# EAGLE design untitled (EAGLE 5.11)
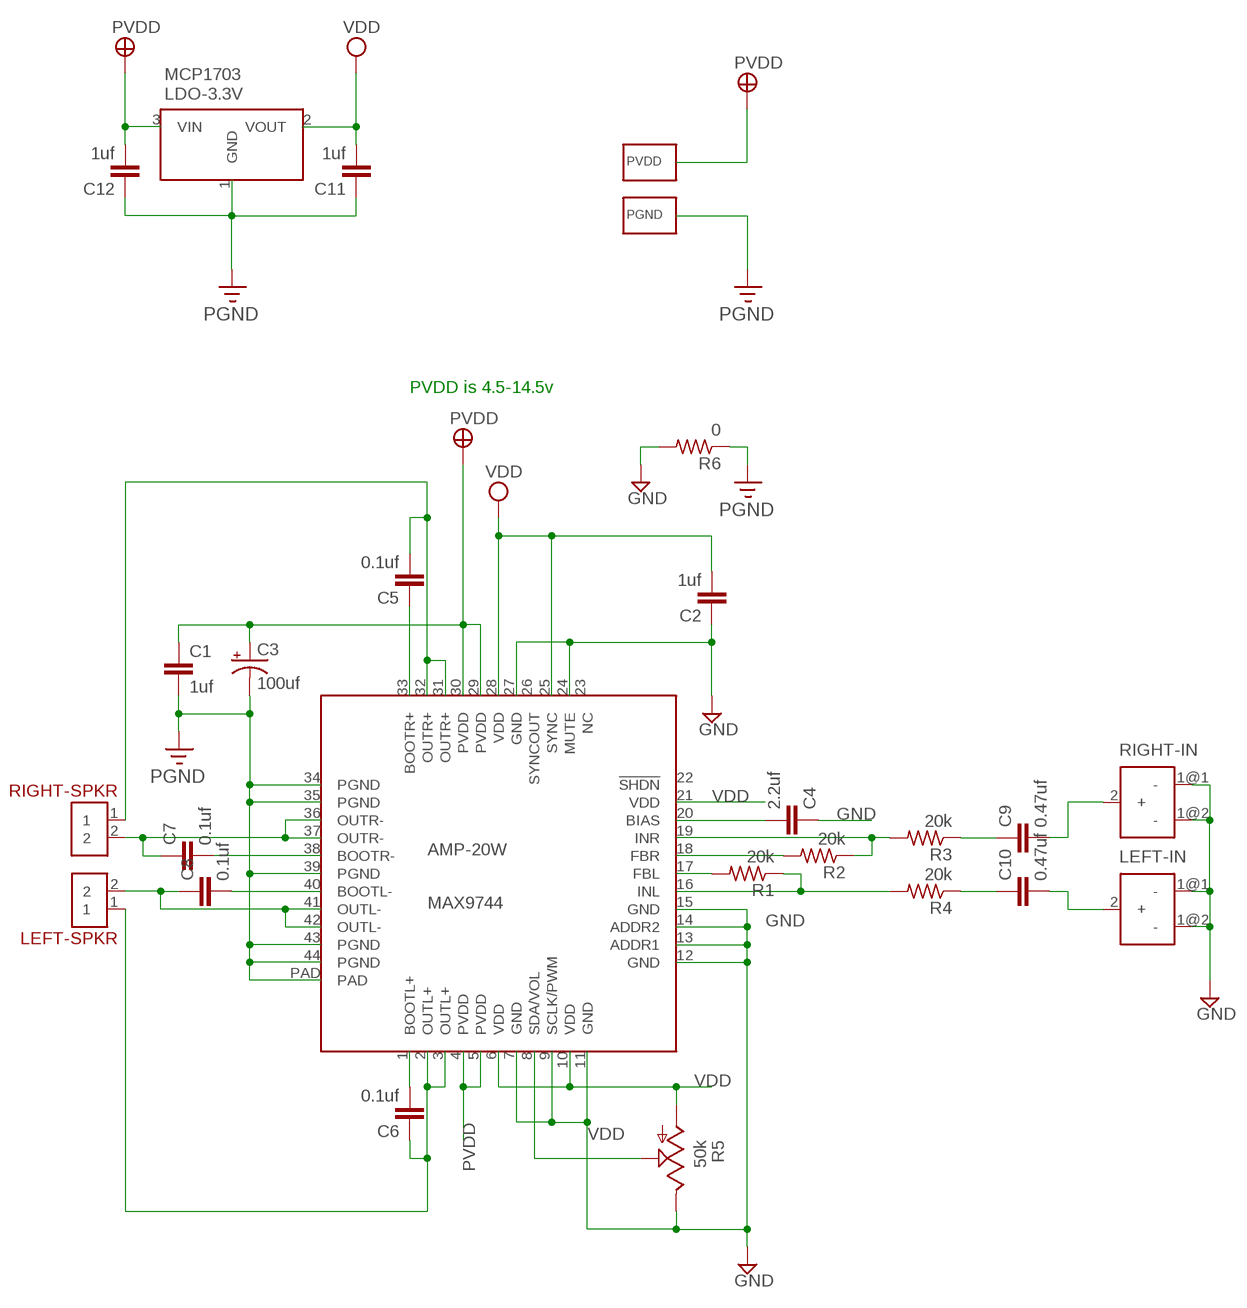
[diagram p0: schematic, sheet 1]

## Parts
AMP-20W  MAX9744  [QFN44-7X7-POWERPAD]
C1  1uf  C-EUC0805  [C0805]
C2  1uf  C-EUC0805  [C0805]
C3  100uf  CPOL-USE  [PANASONIC_E]
C4  2.2uf  C-EUC1206  [C1206]
C5  0.1uf  C-EUC0805  [C0805]
C6  0.1uf  C-EUC0805  [C0805]
C7  0.1uf  C-EUC0805  [C0805]
C8  0.1uf  C-EUC0805  [C0805]
C9  0.47uf  C-EUC1206  [C1206]
C10  0.47uf  C-EUC1206  [C1206]
C11  1uf  C-EUC0805  [C0805]
C12  1uf  C-EUC0805  [C0805]
LDO-3.3V  MCP1703  [SOT23-3]
LEFT-IN  AUDIO-JACK-MONO  [AUDIO-JACK-MONO-SMD]
LEFT-SPKR  SCREW-CLAMP-2X3.5MM  [SCREW-CLAMP-2X3.5MM]
PGND  WIREPAD-SMD-NO-VALUE5X5MM  [WIREPAD-SMD-5X5MM]
PVDD  WIREPAD-SMD-NO-VALUE5X5MM  [WIREPAD-SMD-5X5MM]
R1  20k  R-US_R0805  [R0805]
R2  20k  R-US_R0805  [R0805]
R3  20k  R-US_R0805  [R0805]
R4  20k  R-US_R0805  [R0805]
R5  50k  POT-TRIM-PARALLAX  [POT-TRIM-PARALLAX]
R6  0  R-US_R1206  [R1206]
RIGHT-IN  AUDIO-JACK-MONO  [AUDIO-JACK-MONO-SMD]
RIGHT-SPKR  SCREW-CLAMP-2X3.5MM  [SCREW-CLAMP-2X3.5MM]

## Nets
GND: AMP-20W.7(GND) AMP-20W.9(SCLK/PWM) AMP-20W.11(GND) AMP-20W.12(GND) AMP-20W.13(ADDR1) AMP-20W.14(ADDR2) AMP-20W.15(GND) AMP-20W.24(MUTE) AMP-20W.27(GND) C2.1 C4.1 LEFT-IN.1@1(-) LEFT-IN.1@2(-) R5.3(E) R6.2 RIGHT-IN.1@1(-) RIGHT-IN.1@2(-)
N$1: AMP-20W.16(INL) R1.1 R4.2
N$2: AMP-20W.18(FBR) R2.2
N$3: AMP-20W.17(FBL) R1.2
N$4: AMP-20W.19(INR) R2.1 R3.2
N$5: AMP-20W.36(OUTR-) AMP-20W.37(OUTR-) C7.1 RIGHT-SPKR.2
N$6: C10.1 R4.1
N$7: AMP-20W.41(OUTL-) AMP-20W.42(OUTL-) C8.1 LEFT-SPKR.2
N$8: AMP-20W.40(BOOTL-) C8.2
N$9: AMP-20W.38(BOOTR-) C7.2
N$10: AMP-20W.2(OUTL+) AMP-20W.3(OUTL+) C6.1 LEFT-SPKR.1
N$11: AMP-20W.31(OUTR+) AMP-20W.32(OUTR+) C5.2 RIGHT-SPKR.1
N$12: AMP-20W.20(BIAS) C4.2
N$13: AMP-20W.1(BOOTL+) C6.2
N$14: AMP-20W.33(BOOTR+) C5.1
N$15: C9.1 R3.1
N$17: AMP-20W.8(SDA/VOL) R5.2(S)
N$19: C9.2 RIGHT-IN.2(+)
N$20: C10.2 LEFT-IN.2(+)
PGND: AMP-20W.34(PGND) AMP-20W.35(PGND) AMP-20W.39(PGND) AMP-20W.43(PGND) AMP-20W.44(PGND) AMP-20W.PAD C1.2 C3.- C11.1 C12.1 LDO-3.3V.1(GND) PGND.1(P) R6.1
PVDD: AMP-20W.4(PVDD) AMP-20W.5(PVDD) AMP-20W.29(PVDD) AMP-20W.30(PVDD) C1.1 C3.+ C12.2 LDO-3.3V.3(VIN) PVDD.1(P)
VDD: AMP-20W.6(VDD) AMP-20W.10(VDD) AMP-20W.21(VDD) AMP-20W.25(SYNC) AMP-20W.28(VDD) C2.2 C11.2 LDO-3.3V.2(VOUT) R5.1(A)
Unconnected: AMP-20W.22(!SHDN) AMP-20W.23(NC) AMP-20W.26(SYNCOUT)

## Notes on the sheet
- PVDD is 4.5-14.5v

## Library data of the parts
AMP-20W = trl:MAX9744
C1 C2 C4-C12 = rcl:C-EU: CAPACITOR, European symbol
C3 = rcl:CPOL-US: POLARIZED CAPACITOR, American symbol
LDO-3.3V = trl:MCP1703
LEFT-IN RIGHT-IN = trl:AUDIO-JACK-MONO
LEFT-SPKR RIGHT-SPKR = trl:SCREW-CLAMP-2X3.5MM
PGND PVDD = trl:WIREPAD-SMD-NO-VALUE
R1-R4 R6 = resistor:R-US_: RESISTOR, American symbol
R5 = trl:POT-TRIM-PARALLAX: POTENTIOMETER

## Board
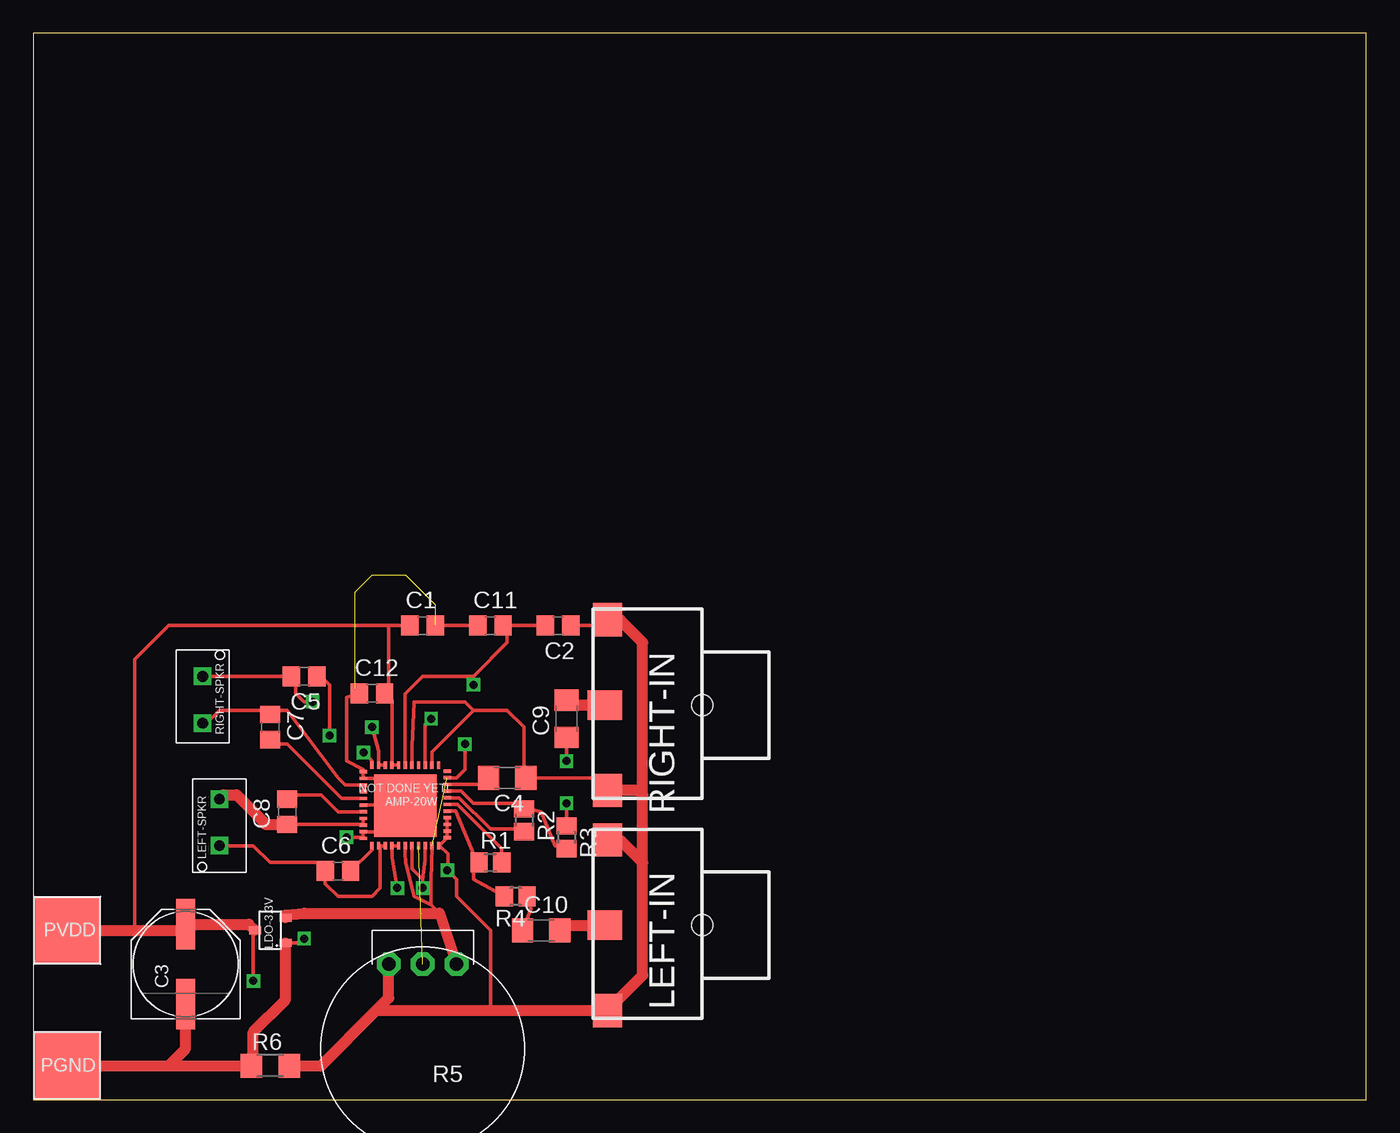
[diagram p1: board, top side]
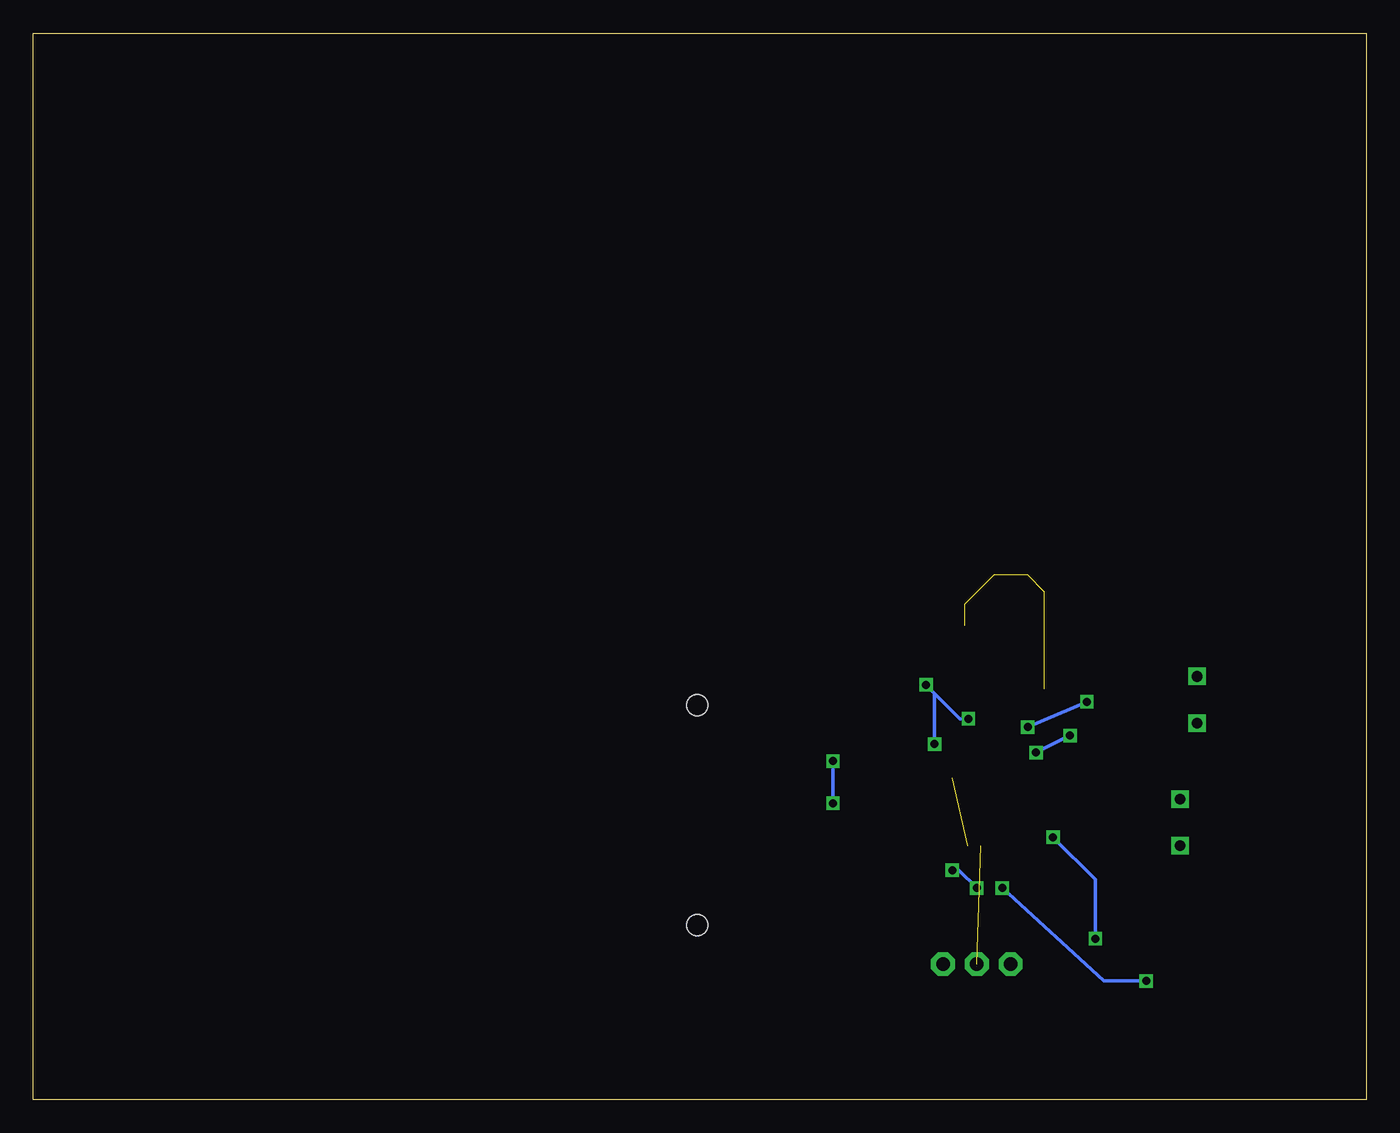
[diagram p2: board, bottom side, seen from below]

Size 100 x 80 mm. Coordinates in mm from the lower left corner, seen from the top.
Outline: 0,0 100,0 100,80 0,80 0,0
Copper layers (1*16): Top 0.035mm / dielectric 1.5mm / Bottom 0.035mm
Design rules "default": minimum track width 10mil, minimum drill 0.6mm, track to track 8mil, track to pad 8mil, pad to pad 8mil, via to via 8mil, smd to smd 8mil, copper to edge 40mil, drill to drill 8mil, minimum pad ring 10mil, minimum via ring 8mil, stop-mask expansion 4mil, vias tented up to drill 0mil, thermal gap 10mil

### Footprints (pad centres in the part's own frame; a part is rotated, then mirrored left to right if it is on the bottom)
QFN44-7X7-POWERPAD = smd 0.25 x 0.55: 1 0,0; 2 0.5,0; 3 1,0; 4 1.5,0; 5 2,0; 6 2.5,0; 7 3,0; 8 3.5,0; 9 4,0; 10 4.5,0; 11 5,0; 23 5,6.05; 24 4.5,6.05; 25 4,6.05; 26 3.5,6.05; 27 3,6.05; 28 2.5,6.05; 29 2,6.05; 30 1.5,6.05; 31 1,6.05; 32 0.5,6.05; 33 0,6.05 | smd 0.55 x 0.25: 12 5.65,0.6; 13 5.65,1.1; 14 5.65,1.6; 15 5.65,2.1; 16 5.65,2.6; 17 5.65,3.1; 18 5.65,3.6; 19 5.65,4.1; 20 5.65,4.6; 21 5.65,5.1; 22 5.65,5.6; 34 -0.65,5.55; 35 -0.65,5.05; 36 -0.65,4.55; 37 -0.65,4.05; 38 -0.65,3.55; 39 -0.65,3.05; 40 -0.65,2.55; 41 -0.65,2.05; 42 -0.65,1.55; 43 -0.65,1.05; 44 -0.65,0.55 | smd 4.7 x 4.7: PAD 2.5,3
C0805 = smd 1.3 x 1.5: 1 -0.95,0; 2 0.95,0
PANASONIC_E = smd 3.8 x 1.4: + 3,0; - -3,0
C1206 = smd 1.6 x 1.8: 1 -1.4,0; 2 1.4,0
SOT23-3 = smd 0.6 x 0.9: 1 -0.95,-1.15; 2 0.95,-1.15; 3 0,1.15
AUDIO-JACK-MONO-SMD = smd 2.2 x 2.5: 1@1 0.1,-14.4; 1@2 0.1,-1.6 | smd 2.6 x 2.2: 2 0.3,-8 | hole 1.6: -7,-8
SCREW-CLAMP-2X3.5MM = drill 0.8 square: 1 0,0; 2 3.5,0
WIREPAD-SMD-5X5MM = smd 5 x 5: 1 0,0
R0805 = smd 1.3 x 1.5: 1 -0.85,0; 2 0.85,0
POT-TRIM-PARALLAX = drill 1.016 pad 1.778 octagon: 1 -2.54,-3.81; 2 0,-3.81; 3 2.54,-3.81
R1206 = smd 1.6 x 1.803: 1 -1.422,0; 2 1.422,0

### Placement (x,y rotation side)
AMP-20W  25.4,19.05 0 top
C1  29.21,35.56 0 top
C2  39.37,35.56 180 top
C3  11.43,10.16 90 top
C4  35.56,24.13 180 top
C5  20.32,31.75 180 top
C6  22.86,17.14 0 top
C7  17.78,27.94 270 top
C8  19.05,21.59 90 top
C9  40.01,28.57 90 top
C10  38.1,12.7 0 top
C11  34.29,35.56 0 top
C12  25.4,30.48 0 top
LDO-3.3V  17.78,12.7 90 top
LEFT-IN  43.18,5.08 180 top
LEFT-SPKR  13.97,19.05 90 top
PGND  2.54,2.54 90 top
PVDD  2.54,12.7 90 top
R1  34.29,17.78 0 top
R2  36.83,20.95 270 top
R3  40.01,19.68 270 top
R4  36.2,15.24 180 top
R5  29.21,6.35 180 top
R6  17.78,2.54 0 top
RIGHT-IN  43.18,21.59 180 top
RIGHT-SPKR  12.7,31.75 270 top

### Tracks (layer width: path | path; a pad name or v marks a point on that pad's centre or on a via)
GND  (via drill 0.6)
  Top 0.254: AMP-20W.12 AMP-20W.13 AMP-20W.14 AMP-20W.15 | AMP-20W.12 31,19.65 | RIGHT-IN.1@2 42.14,24.13 C4.1 36.83,24.26 36.83,27.94 35.56,29.21 33.02,29.21 | 34.29,6.68 34.29,12.7 31.75,15.24 31.75,16.51 v31.05,17.21 31.11,17.27 31.11,18.41 30.48,19.05 AMP-20W.11 30.45,19.05 AMP-20W.12 | AMP-20W.9 29.4,17.97 29.21,16.51 | AMP-20W.7 28.4,17.32 29.21,16.51 | C2.1 42.65,35.56 RIGHT-IN.1@1 | v29.21,15.88 29.21,16.51 | AMP-20W.27 28.4,26.5 28.57,29.84 32.38,29.84 33.02,29.21 | AMP-20W.24 29.9,26.09 33.02,29.21
  Top 0.813: 25.73,6.68 26.67,7.62 R5.3 | 25.73,6.68 34.29,6.68 LEFT-IN.1@2 45.72,9.32 45.72,17.78 | LEFT-IN.1@1 44.02,19.48 45.72,17.78 | RIGHT-IN.1@2 45.39,23.19 45.72,22.86 | 45.72,17.78 45.72,22.86 | RIGHT-IN.1@1 44.02,35.99 45.72,34.29 45.72,22.86 | R6.2 21.59,2.54 25.73,6.68
  Bottom 0.254: v31.05,17.21 30.55,17.21 v29.21,15.88
N$1
  Top 0.254: R4.2 33.02,16.51 33.02,17.36 R1.1 33.02,18.2 33.02,18.41 31.69,21.65 AMP-20W.16
N$2
  Top 0.254: AMP-20W.18 31.96,22.65 34.29,20.32 36.62,20.32 R2.2
N$3
  Top 0.254: AMP-20W.17 31.82,22.15 35.14,18.84 R1.2
N$4
  Top 0.254: AMP-20W.19 32.09,23.15 33.02,22.23 36.41,22.23 R2.1 37.25,21.8 38.1,21.59 39.16,19.05 R3.2
N$5
  Top 0.254: AMP-20W.37 AMP-20W.36 23.39,23.6 22.86,24.13 19.05,29.21 18.1,29.21 C7.1 17.46,29.21 13.97,29.21 13.01,28.25 RIGHT-SPKR.2
N$6
  Top 0.254: C10.1 37.34,14.31 R4.1
N$7
  Top 0.254: AMP-20W.41 AMP-20W.42 24.71,20.64 C8.1
  Top 0.813: C8.1 17.46,20.64 15.24,22.86 14.28,22.86 LEFT-SPKR.2
N$8
  Top 0.254: AMP-20W.40 22.85,21.6 21.59,22.86 19.37,22.86 C8.2
N$9
  Top 0.254: AMP-20W.38 23.12,22.6 19.05,26.67 18.1,26.67 C7.2
N$10
  Top 0.254: AMP-20W.3 AMP-20W.2 26.04,18.91 26.04,15.88 25.4,15.24 22.86,15.24 21.91,16.19 C6.1 21.27,17.78 17.78,17.78 16.51,19.05 LEFT-SPKR.1
N$11  (via drill 0.6)
  Top 0.254: AMP-20W.31 AMP-20W.32 25.9,26.17 v25.4,27.94 | RIGHT-SPKR.1 C5.2 19.68,31.43 19.68,30.48 20.32,29.84 v20.95,29.84
  Bottom 0.254: v20.95,29.84 v25.4,27.94
N$12
  Top 0.254: AMP-20W.20 33.68,23.65 C4.2
N$13
  Top 0.254: AMP-20W.1 25.4,18.73 C6.2
N$14  (via drill 0.6)
  Top 0.254: C5.1 21.59,31.75 22.23,31.11 v22.23,27.3 | AMP-20W.33 25.4,25.4 v24.77,26.04
  Bottom 0.254: v22.23,27.3 v24.77,26.04
N$15  (via drill 0.6)
  Top 0.254: R3.1 v40.01,22.23 | v40.01,25.4 C9.1
  Bottom 0.254: v40.01,22.23 v40.01,25.4
N$17  (1 unrouted)
N$19
  Top 0.813: RIGHT-IN.2 39.88,29.59 C9.2
N$20
  Top 0.813: LEFT-IN.2 39.88,13.08 C10.2
PGND  (via drill 0.6)  (5 unrouted)
  Top 0.254: AMP-20W.39 27.85,22.1 AMP-20W.PAD | AMP-20W.PAD 26.67,20.82 26.67,20.32 26.45,20.1 AMP-20W.43 AMP-20W.44 24.66,19.68 v23.5,19.68 | AMP-20W.PAD 25.85,24.1 AMP-20W.35 AMP-20W.34 24.75,24.78 23.5,25.4 23.5,30.16 C12.1 24.13,30.8 | LDO-3.3V.1 20,11.75 v20.32,12.06 | C1.2 C11.1
  Top 0.813: PGND.1 10.16,2.54 | C3.- 11.43,3.81 10.16,2.54 | LDO-3.3V.1 18.93,7.5 16.51,5.08 16.51,2.69 R6.1 10.16,2.54
  Bottom 0.254: v20.32,12.06 20.32,16.51 v23.5,19.68
PVDD  (via drill 0.6)
  Top 0.254: AMP-20W.5 AMP-20W.4 26.9,18.18 v27.3,15.88 | AMP-20W.29 AMP-20W.30 26.9,29.93 C12.2 26.67,30.8 26.67,35.56 | v16.51,8.89 16.51,12.82 LDO-3.3V.3 | 26.67,35.56 10.16,35.56 7.62,33.02 7.62,12.7 | 26.67,35.56 C1.1
  Top 0.813: PVDD.1 7.62,12.7 10.97,12.7 C3.+ 16.17,13.16 LDO-3.3V.3
  Bottom 0.254: v27.3,15.88 19.68,8.89 v16.51,8.89
VDD  (via drill 0.6)  (1 unrouted)
  Top 0.254: AMP-20W.6 27.9,18.45 27.94,17.78 28.57,15.24 29.84,14.61 | 29.84,14.61 29.84,16.45 AMP-20W.10 | C2.2 C11.2 35.56,35.24 35.56,34.29 33.02,31.75 | 31.77,24.15 AMP-20W.21 | 30.48,13.97 29.84,14.61 | AMP-20W.28 27.9,30.44 29.21,31.75 33.02,31.75 | AMP-20W.25 29.4,28.13 v29.84,28.57 | 33.02,31.75 v33.02,31.11 | 31.77,24.15 31.75,24.13 | 31.77,24.15 32.38,24.77 v32.38,26.67
  Top 0.813: LDO-3.3V.2 18.93,13.85 20.32,13.97 30.48,13.97 R5.1
  Bottom 0.254: v29.84,28.57 30.48,28.57 32.38,30.48 | v33.02,31.11 32.38,30.48 | 32.38,30.48 v32.38,26.67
